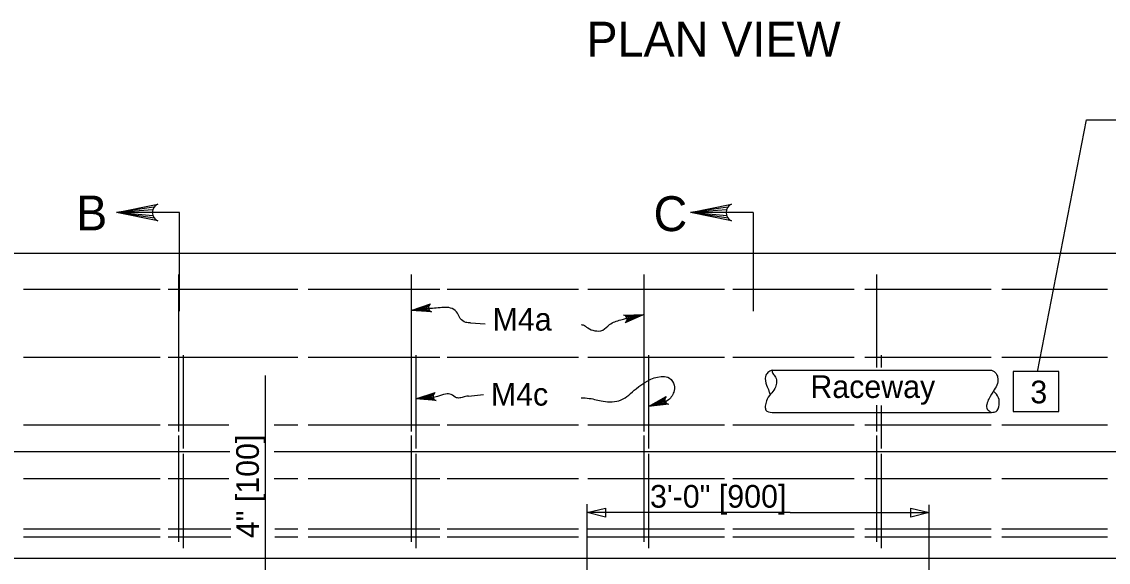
# Model space of a CAD drawing. Extents: x 0 to 34, y 0 to 22.
# Drawn here: x 5.5 to 12.97, y 6.55 to 10.27 of the extents above; entities that cross this region are included whole.
import ezdxf

# ---------------------------------------------------------------- set-up
doc = ezdxf.new("R2010")
doc.units = 0
doc.layers.add('Default', color=7, linetype='Continuous')
doc.layers.add('SH_Text', color=7, linetype='Continuous')

msp = doc.modelspace()

# ---------------------------------------------------------------- linework, layer by layer
at = {"layer": 'Default'}
for p, q in [((6.408, 8.9923), (6.1516, 8.9565)), ((6.3993, 8.9746), (6.1516, 8.9565)), ((10.3528, 8.9923), (10.0964, 8.9565)), ((10.3441, 8.9746), (10.0964, 8.9565)), ((6.5843, 8.9565), (6.1516, 8.9565)), ((6.3966, 8.9565), (6.1516, 8.9565)), ((6.4012, 8.9334), (6.1516, 8.9565)), ((6.411, 8.9168), (6.1516, 8.9565)), ((6.5843, 8.2768), (6.5843, 8.9565)), ((10.529, 8.9565), (10.0964, 8.9565)), ((10.3415, 8.9565), (10.0964, 8.9565)), ((10.346, 8.9334), (10.0964, 8.9565)), ((10.3558, 8.9168), (10.0964, 8.9565)), ((10.529, 8.9565), (10.529, 8.2768)), ((2.6198, 8.6767), (18.4339, 8.6767)), ((6.5778, 8.5296), (6.5778, 7.4504)), ((8.177, 8.5296), (8.177, 7.4504)), ((9.7763, 8.5296), (9.7763, 7.4504)), ((11.3755, 8.5296), (11.3755, 7.8905)), ((5.5105, 8.4278), (6.4512, 8.4278)), ((6.5065, 8.4278), (7.398, 8.4278)), ((7.4685, 8.4278), (8.3727, 8.4278)), ((8.4234, 8.4278), (9.3268, 8.4278)), ((9.3917, 8.4278), (10.3306, 8.4278)), ((10.3877, 8.4278), (11.2214, 8.4278)), ((11.2959, 8.4278), (12.1635, 8.4278)), ((12.2372, 8.4278), (12.964, 8.4278)), ((8.2982, 8.3152), (8.177, 8.2818)), ((8.2951, 8.3062), (8.177, 8.2818)), ((8.295, 8.2973), (8.177, 8.2818)), ((8.2986, 8.2865), (8.177, 8.2818)), ((8.3044, 8.2791), (8.177, 8.2818)), ((9.6494, 8.2452), (9.7763, 8.2553)), ((9.6558, 8.2385), (9.7763, 8.2553)), ((9.6591, 8.2099), (9.7763, 8.2553)), ((9.6605, 8.2281), (9.7763, 8.2553)), ((9.6613, 8.2192), (9.7763, 8.2553)), ((8.5845, 8.1981), (8.6846, 8.1902)), ((5.5105, 7.9607), (6.4512, 7.9607)), ((6.5065, 7.9607), (7.398, 7.9607)), ((6.6092, 7.975), (6.6092, 7.3332)), ((7.4685, 7.9607), (8.3727, 7.9607)), ((8.2085, 7.975), (8.2085, 7.3332)), ((8.4234, 7.9607), (9.3268, 7.9607)), ((9.3917, 7.9607), (10.3306, 7.9607)), ((9.8077, 7.975), (9.8077, 7.3332)), ((10.3877, 7.9607), (11.2214, 7.9607)), ((11.2959, 7.9607), (12.1635, 7.9607)), ((11.407, 7.975), (11.407, 7.8905)), ((12.2372, 7.9607), (12.964, 7.9607)), ((10.6584, 7.8726), (12.1676, 7.8726)), ((12.3161, 7.8635), (12.3161, 7.588)), ((12.6305, 7.8635), (12.3161, 7.8635)), ((12.6305, 7.588), (12.6305, 7.8635)), ((7.176, 6.2192), (7.176, 7.8345)), ((8.3304, 7.7057), (8.2085, 7.6756)), ((8.3271, 7.6967), (8.2085, 7.6756)), ((8.5715, 7.6932), (8.6742, 7.7043)), ((8.3267, 7.6878), (8.2085, 7.6756)), ((8.33, 7.6769), (8.2085, 7.6756)), ((8.3356, 7.6694), (8.2085, 7.6756)), ((9.9208, 7.6773), (9.8077, 7.6227)), ((9.9195, 7.6678), (9.8077, 7.6227)), ((9.9209, 7.6591), (9.8077, 7.6227)), ((9.9265, 7.6491), (9.8077, 7.6227)), ((9.9335, 7.6429), (9.8077, 7.6227)), ((11.3755, 7.6318), (11.3755, 7.4504)), ((11.407, 7.6295), (11.407, 7.3332)), ((10.6584, 7.5816), (12.1676, 7.5816)), ((12.3161, 7.588), (12.6305, 7.588)), ((5.5105, 7.495), (6.4512, 7.495)), ((6.5065, 7.495), (6.9233, 7.495)), ((7.2347, 7.495), (7.398, 7.495)), ((7.4685, 7.495), (8.3727, 7.495)), ((8.4234, 7.495), (9.3268, 7.495)), ((9.3917, 7.495), (10.3306, 7.495)), ((10.3877, 7.495), (11.2214, 7.495)), ((11.2959, 7.495), (12.1635, 7.495)), ((12.2372, 7.495), (12.964, 7.495)), ((6.5778, 7.4229), (6.5778, 6.6903)), ((8.177, 7.4229), (8.177, 6.6903)), ((9.7763, 7.4229), (9.7763, 6.6903)), ((11.3755, 7.4229), (11.3755, 6.6903)), ((2.6486, 7.3117), (6.9296, 7.3117)), ((6.6092, 7.2958), (6.6092, 6.6482)), ((7.2347, 7.3117), (15.3565, 7.3117)), ((8.2085, 7.2958), (8.2085, 6.6482)), ((9.8077, 7.2958), (9.8077, 6.6482)), ((11.407, 7.2958), (11.407, 6.6482)), ((5.5105, 7.1266), (6.4512, 7.1266)), ((6.5065, 7.1266), (6.9233, 7.1266)), ((7.2347, 7.1266), (7.398, 7.1266)), ((7.4685, 7.1266), (8.3727, 7.1266)), ((8.4234, 7.1266), (9.3268, 7.1266)), ((9.3917, 7.1266), (10.3306, 7.1266)), ((10.3877, 7.1266), (11.2214, 7.1266)), ((11.2959, 7.1266), (12.1635, 7.1266)), ((12.2372, 7.1266), (12.964, 7.1266)), ((9.3866, 6.3722), (9.3866, 6.9509)), ((10.7826, 6.8919), (9.3866, 6.8919)), ((10.7826, 6.8919), (11.7375, 6.8919)), ((11.7375, 6.3647), (11.7375, 6.9456)), ((5.5105, 6.7807), (6.4512, 6.7807)), ((5.5105, 6.7256), (6.4512, 6.7256)), ((6.5065, 6.7807), (6.9375, 6.7807)), ((6.5065, 6.7256), (6.9375, 6.7256)), ((7.2385, 6.7807), (7.398, 6.7807)), ((7.2385, 6.7256), (7.398, 6.7256)), ((7.4685, 6.7807), (8.3727, 6.7807)), ((7.4685, 6.7256), (8.3727, 6.7256)), ((8.4234, 6.7807), (9.3268, 6.7807)), ((8.4234, 6.7256), (9.3268, 6.7256)), ((9.3917, 6.7807), (10.3306, 6.7807)), ((9.3917, 6.7256), (10.3306, 6.7256)), ((10.3877, 6.7807), (11.2214, 6.7807)), ((10.3877, 6.7256), (11.2214, 6.7256)), ((11.2959, 6.7807), (12.1635, 6.7807)), ((11.2959, 6.7256), (12.1635, 6.7256)), ((12.2372, 6.7807), (12.964, 6.7807)), ((12.2372, 6.7256), (12.964, 6.7256)), ((2.6486, 6.5793), (15.3309, 6.5793))]:
    msp.add_line(p, q, dxfattribs=at)
for points in [[(6.4348, 8.8998), (6.1516, 8.9565), (6.4348, 9.0131)], [(10.3796, 8.8998), (10.0964, 8.9565), (10.3796, 9.0131)], [(8.3169, 8.2725), (8.177, 8.2818), (8.3098, 8.327)], [(9.6362, 8.2506), (9.7763, 8.2553), (9.6488, 8.1971)], [(8.348, 7.6624), (8.2085, 7.6756), (8.3423, 7.7171)], [(9.947, 7.6386), (9.8077, 7.6227), (9.9301, 7.6908)]]:
    msp.add_lwpolyline(points, dxfattribs=at)
for points in [[(9.5115, 6.8607), (9.3866, 6.8919), (9.5115, 6.9232)], [(11.6125, 6.9232), (11.7375, 6.8919), (11.6125, 6.8607)]]:
    msp.add_lwpolyline(points, close=True, dxfattribs=at)
for centre in [(6.4577, 8.9565), (10.4025, 8.9565)]:
    msp.add_arc(centre, 0.0611, 112.08782, 247.91395, dxfattribs=at)
for centre, major_axis, start_param, end_param in [((8.3244, 8.3011), (-0.0297, 0), 5.228004, 7.598617), ((9.6317, 8.2213), (0.0297, 0), 5.328938, 7.699551), ((8.3562, 7.6909), (-0.0297, 0), 5.200961, 7.571574), ((9.9492, 7.6681), (-0.0297, 0), 5.408547, 7.77916)]:
    msp.add_ellipse(centre, major_axis=major_axis, ratio=0.999895, start_param=start_param, end_param=end_param, dxfattribs=at)
for points in [[(8.5846, 8.198), (8.5517, 8.2002), (8.5142, 8.2267), (8.4945, 8.2642), (8.4592, 8.2951), (8.3624, 8.2994), (8.261, 8.2928), (8.177, 8.2818)], [(9.3445, 8.1853), (9.3595, 8.1827), (9.3904, 8.1627), (9.4388, 8.1429), (9.4938, 8.1473), (9.54, 8.1848), (9.6171, 8.2179), (9.7763, 8.2553)], [(10.6584, 7.8726), (10.6298, 7.8555), (10.613, 7.8287), (10.62, 7.7685), (10.6365, 7.728), (10.6458, 7.7038)], [(10.6584, 7.8726), (10.663, 7.8485), (10.6811, 7.8244), (10.6881, 7.783), (10.6769, 7.7452), (10.6482, 7.7073), (10.6195, 7.6608), (10.6115, 7.623), (10.6153, 7.5971), (10.6584, 7.5816)], [(12.1676, 7.8726), (12.1976, 7.8491), (12.2086, 7.8232), (12.2085, 7.7802), (12.1845, 7.7363), (12.1494, 7.6761), (12.1342, 7.6365), (12.1373, 7.6037), (12.1676, 7.5816)], [(9.3445, 7.6825), (9.4014, 7.6778), (9.496, 7.6579), (9.6193, 7.6668), (9.7228, 7.744), (9.8945, 7.8277), (9.9407, 7.8233), (9.9804, 7.7814), (9.9847, 7.7307), (9.9451, 7.6668), (9.8077, 7.6227)], [(8.5715, 7.6932), (8.5495, 7.6911), (8.5186, 7.6822), (8.4879, 7.6822), (8.4526, 7.7042), (8.413, 7.7064), (8.3579, 7.6911), (8.2085, 7.6756)], [(12.1676, 7.5816), (12.1981, 7.5872), (12.219, 7.6328), (12.2151, 7.6819), (12.1798, 7.7281)]]:
    msp.add_spline(points, degree=3, dxfattribs=at)
at = {"layer": 'SH_Text'}
for p, q in [((12.4818, 7.8599), (12.8203, 9.5929)), ((12.8203, 9.5929), (13.0424, 9.5929))]:
    msp.add_line(p, q, dxfattribs=at)

# ---------------------------------------------------------------- texts
at = {"layer": 'Default'}
for s, height, p in [('PLAN VIEW', 0.24, (9.3816, 10.0285)), ('B', 0.24, (5.8731, 8.8329)), ('C', 0.24, (9.8432, 8.8281)), ('M4a', 0.156, (8.7362, 8.1439)), ('M4c', 0.156, (8.7246, 7.6279)), ('Raceway', 0.156, (10.9215, 7.6804)), ('3', 0.156, (12.4335, 7.6437)), ('3\'-0" [900]', 0.156, (9.8189, 6.9259))]:
    msp.add_text(s, height=height, dxfattribs=at).set_placement(p)
msp.add_text('4" [100]', height=0.156, rotation=90, dxfattribs=at).set_placement((7.1295, 6.716))

doc.saveas('drawing.dxf')
